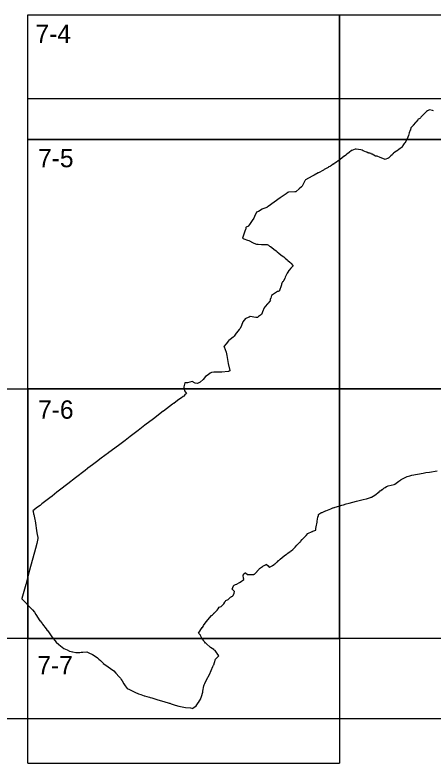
# Model space of a CAD drawing. Extents: x -449577 to -425530, y -1150048 to -1121091.
# Drawn here: x -443343.3 to -443133.6, y -1126653.4 to -1126278.4 of the extents above; entities that cross this region are included whole.
import ezdxf

# ---------------------------------------------------------------- set-up
doc = ezdxf.new("R2010")
doc.units = 0
for name, color, linetype in [('Vrstva 1', 7, 'Continuous'), ('Vrstva 10', 7, 'Continuous'), ('Vrstva 4', 7, 'Continuous')]:
    doc.layers.add(name, color=color, linetype=linetype)

msp = doc.modelspace()

# ---------------------------------------------------------------- linework, layer by layer
at = {"layer": 'Vrstva 1'}
for points in [[(-443133.39, -1126326.41), (-443133.85, -1126326.32), (-443135.44, -1126326), (-443135.74, -1126326.11), (-443136.3, -1126326.46), (-443136.85, -1126326.78), (-443137.34, -1126327.24), (-443137.87, -1126327.73), (-443138.27, -1126328.12), (-443138.28, -1126328.13), (-443138.61, -1126328.47), (-443138.74, -1126328.61), (-443139.25, -1126329.16), (-443139.7, -1126329.71), (-443139.86, -1126329.9), (-443140.22, -1126330.33), (-443140.96, -1126330.66), (-443140.98, -1126330.66), (-443141.18, -1126330.91), (-443142.04, -1126331.93), (-443142.42, -1126332.38), (-443143.55, -1126333.74), (-443143.56, -1126333.75), (-443144.8, -1126334.92), (-443144.92, -1126335.76), (-443144.97, -1126336.13), (-443145.01, -1126336.23), (-443145.49, -1126337.58), (-443145.93, -1126338.82), (-443145.96, -1126338.9), (-443146.26, -1126339.59), (-443147.19, -1126341.77), (-443147.21, -1126341.78), (-443147.78, -1126342.46), (-443148.08, -1126342.81), (-443148.08, -1126342.82), (-443148.42, -1126343.36), (-443149.29, -1126344.75), (-443149.38, -1126344.89), (-443149.55, -1126345.02), (-443150.08, -1126345.41), (-443150.69, -1126345.86), (-443150.69, -1126345.86), (-443151.66, -1126346.49), (-443151.79, -1126346.58), (-443151.97, -1126346.7), (-443153.27, -1126347.56), (-443153.28, -1126347.57), (-443153.54, -1126347.83), (-443153.66, -1126347.95), (-443153.88, -1126348.18), (-443154.16, -1126348.46), (-443154.73, -1126349.03), (-443155.89, -1126350.19), (-443156.09, -1126350.27), (-443157.59, -1126350.84), (-443160.4, -1126349.72), (-443160.4, -1126349.73), (-443160.41, -1126349.75), (-443161.32, -1126349.37), (-443161.63, -1126349.24), (-443161.65, -1126349.24), (-443162.04, -1126349.24), (-443162.52, -1126349.24), (-443164.08, -1126348.25), (-443164.34, -1126348.12), (-443164.63, -1126347.96), (-443164.69, -1126347.93), (-443164.73, -1126347.91), (-443165.27, -1126347.68), (-443165.32, -1126347.68), (-443165.33, -1126347.68), (-443165.48, -1126347.67), (-443165.6, -1126347.66), (-443165.91, -1126347.64), (-443165.93, -1126347.64), (-443165.93, -1126347.64), (-443166.04, -1126347.6), (-443166.28, -1126347.5), (-443166.88, -1126347.25), (-443167.04, -1126347.18), (-443168.56, -1126346.45), (-443169.18, -1126346.27), (-443169.85, -1126346.07), (-443172.17, -1126345.64), (-443172.18, -1126345.64), (-443172.58, -1126345.75), (-443174.32, -1126346.33), (-443174.45, -1126346.44), (-443175.66, -1126347.4), (-443175.66, -1126347.4), (-443176.81, -1126348.27), (-443177.38, -1126348.7), (-443177.96, -1126349.14), (-443178.12, -1126349.26), (-443180.25, -1126350.9), (-443181.32, -1126351.72), (-443181.79, -1126352.06), (-443182.55, -1126352.57), (-443182.8, -1126352.73), (-443183.39, -1126353.12), (-443183.43, -1126353.15), (-443183.64, -1126353.29), (-443184.55, -1126353.89), (-443184.56, -1126353.89), (-443185.03, -1126354.15), (-443185.18, -1126354.23), (-443185.36, -1126354.33), (-443185.82, -1126354.58), (-443186, -1126354.69), (-443186.16, -1126354.78), (-443186.26, -1126354.84), (-443186.5, -1126354.98), (-443188.16, -1126355.92), (-443188.33, -1126356.01), (-443188.56, -1126356.14), (-443191.03, -1126357.54), (-443191.15, -1126357.61), (-443193.26, -1126358.74), (-443194.28, -1126359.29), (-443197.62, -1126361.1), (-443197.79, -1126361.4), (-443197.85, -1126361.51), (-443198.63, -1126362.97), (-443199.31, -1126364.29), (-443199.45, -1126364.42), (-443199.54, -1126364.5), (-443200.68, -1126365.54), (-443202.19, -1126366.92), (-443202.36, -1126367.07), (-443202.36, -1126367.08), (-443202.83, -1126367.09), (-443206.02, -1126367.18), (-443206.03, -1126367.18), (-443206.46, -1126367.47), (-443207.29, -1126368.04), (-443209.76, -1126369.7), (-443209.8, -1126369.72), (-443210.04, -1126369.9), (-443210.31, -1126370.1), (-443213.29, -1126372.23), (-443213.36, -1126372.28), (-443216.36, -1126374.46), (-443216.83, -1126374.8), (-443216.99, -1126374.86), (-443218.93, -1126375.58), (-443218.94, -1126375.58), (-443219.33, -1126375.82), (-443221.21, -1126376.98), (-443222.13, -1126377.19), (-443222.38, -1126377.7), (-443223.14, -1126379.21), (-443223.15, -1126379.22), (-443223.22, -1126379.48), (-443223.42, -1126380.32), (-443224.25, -1126381.43), (-443225.62, -1126383.38), (-443226.18, -1126384.19), (-443226.21, -1126384.21), (-443227.37, -1126384.85), (-443227.47, -1126384.91), (-443227.54, -1126385.3), (-443227.69, -1126386.11), (-443227.74, -1126386.3), (-443229.03, -1126389.88), (-443229.2, -1126390.36), (-443229.17, -1126390.35), (-443229.15, -1126390.34), (-443228.47, -1126390.6), (-443226.66, -1126391.26), (-443226.04, -1126391.55), (-443223.75, -1126392.63), (-443223.73, -1126392.63), (-443222.57, -1126393.1), (-443222.1, -1126393.28), (-443222.07, -1126393.29), (-443221.64, -1126393.32), (-443221.5, -1126393.33), (-443221.28, -1126393.35), (-443219.68, -1126393.45), (-443218.64, -1126393.52), (-443217.59, -1126393.49), (-443216.75, -1126393.46), (-443216.74, -1126393.46), (-443216.46, -1126393.61), (-443216.09, -1126393.87), (-443215.54, -1126394.25), (-443215.15, -1126394.53), (-443213.59, -1126395.67), (-443213.42, -1126395.79), (-443212.31, -1126396.71), (-443211.92, -1126397.03), (-443211.74, -1126397.18), (-443210.99, -1126397.79), (-443210.72, -1126398.02), (-443210.12, -1126398.51), (-443209.9, -1126398.69), (-443209.26, -1126399.11), (-443208.51, -1126399.61), (-443208.48, -1126399.63), (-443207.72, -1126400.31), (-443206.84, -1126401.09), (-443206.4, -1126401.47), (-443205.39, -1126402.36), (-443205.13, -1126402.59), (-443205.08, -1126402.64), (-443204.98, -1126402.74), (-443204.97, -1126402.75), (-443204.88, -1126402.85), (-443204.85, -1126402.88), (-443203.8, -1126404.11), (-443203.81, -1126404.12), (-443204.25, -1126404.61), (-443204.31, -1126404.68), (-443204.88, -1126405.31), (-443205.7, -1126406.37), (-443205.87, -1126406.58), (-443206.43, -1126407.3), (-443206.73, -1126407.83), (-443206.75, -1126407.87), (-443206.76, -1126407.89), (-443206.89, -1126408.17), (-443207.69, -1126409.84), (-443208, -1126410.48), (-443208.62, -1126411.77), (-443208.73, -1126412.01), (-443208.74, -1126412.01), (-443208.78, -1126412.04), (-443209.07, -1126412.24), (-443209.15, -1126412.28), (-443209.2, -1126412.38), (-443209.29, -1126412.58), (-443209.38, -1126412.86), (-443209.55, -1126413.42), (-443209.56, -1126413.44), (-443209.68, -1126413.94), (-443209.7, -1126414.01), (-443209.69, -1126414.07), (-443209.68, -1126414.15), (-443209.68, -1126414.22), (-443209.69, -1126414.27), (-443210.57, -1126416.6), (-443210.59, -1126416.65), (-443210.61, -1126416.69), (-443210.62, -1126416.7), (-443211.32, -1126417), (-443211.57, -1126417.11), (-443212.04, -1126417.35), (-443214.65, -1126419.04), (-443214.65, -1126419.04), (-443215.02, -1126420.35), (-443215.1, -1126420.61), (-443215.21, -1126421.03), (-443215.27, -1126421.24), (-443215.27, -1126421.25), (-443215.26, -1126421.25), (-443215.09, -1126421.41), (-443215.1, -1126421.42), (-443215.46, -1126421.81), (-443216.26, -1126422.81), (-443216.27, -1126422.82), (-443216.48, -1126423.07), (-443216.48, -1126423.08), (-443216.6, -1126423.23), (-443217.76, -1126424.58), (-443218.3, -1126425.21), (-443219.06, -1126427.16), (-443219.44, -1126428.18), (-443219.57, -1126428.53), (-443221.1, -1126429.63), (-443221.72, -1126430.07), (-443221.9, -1126430.11), (-443221.92, -1126430.11), (-443222.55, -1126430.02), (-443225.39, -1126429.6), (-443225.88, -1126429.84), (-443227.21, -1126430.48), (-443227.75, -1126430.74), (-443227.78, -1126430.77), (-443228.21, -1126431.18), (-443228.38, -1126431.4), (-443229.04, -1126432.25), (-443229.04, -1126432.26), (-443229.71, -1126434.06), (-443230.28, -1126435.56), (-443230.28, -1126435.56), (-443230.42, -1126435.78), (-443230.75, -1126436.15), (-443231.47, -1126436.95), (-443232.17, -1126437.72), (-443232.18, -1126437.74), (-443232.31, -1126437.93), (-443233.38, -1126439.5), (-443233.85, -1126439.88), (-443235.42, -1126441.14), (-443236.09, -1126441.68), (-443236.19, -1126441.76), (-443236.22, -1126441.8), (-443237.34, -1126443.23), (-443238.48, -1126444.54), (-443238.33, -1126444.71), (-443238.32, -1126444.74), (-443238.32, -1126444.75), (-443237.31, -1126447.51), (-443237.03, -1126449.17), (-443236.71, -1126451.12), (-443236.3, -1126453.08), (-443235.57, -1126456.58), (-443235.53, -1126456.78), (-443236.18, -1126457.12), (-443236.3, -1126457.19), (-443239.47, -1126457.45), (-443239.63, -1126457.45), (-443241.12, -1126457.42), (-443243.51, -1126457.4), (-443244.79, -1126457.67), (-443245.39, -1126457.94), (-443246.37, -1126458.74), (-443247.67, -1126459.61), (-443247.76, -1126459.72), (-443248.92, -1126461.14), (-443250.37, -1126462.48), (-443251.06, -1126462.8), (-443251.66, -1126463.08), (-443252.83, -1126463.01), (-443254.44, -1126462.16), (-443256.68, -1126462.83), (-443258.16, -1126462.8), (-443258.54, -1126464.91), (-443258.55, -1126464.93), (-443258.56, -1126465.02), (-443258.27, -1126466.83), (-443257.3, -1126468.15), (-443257.29, -1126468.17), (-443258.03, -1126468.92), (-443258.64, -1126469.48), (-443258.89, -1126469.71), (-443259.69, -1126470.34), (-443261.62, -1126471.57), (-443261.68, -1126471.61), (-443263.65, -1126473.14), (-443263.71, -1126473.18), (-443264.2, -1126473.56), (-443268.86, -1126477.02), (-443268.89, -1126477.05), (-443273.84, -1126480.81), (-443278.1, -1126484.06), (-443278.98, -1126484.72), (-443281.55, -1126486.66), (-443285.55, -1126489.79), (-443287.99, -1126491.66), (-443291.3, -1126494.19), (-443291.35, -1126494.23), (-443296.14, -1126497.74), (-443296.37, -1126497.92), (-443299.98, -1126500.6), (-443302.37, -1126502.42), (-443304.34, -1126503.9), (-443306.66, -1126505.65), (-443306.89, -1126505.82), (-443308.02, -1126506.71), (-443312.84, -1126510.51), (-443316.73, -1126513.46), (-443320.95, -1126516.71), (-443322.24, -1126517.71), (-443324.63, -1126519.59), (-443325.81, -1126520.51), (-443329.75, -1126523.56), (-443330.68, -1126524.27), (-443331.92, -1126525.23), (-443334.24, -1126527.03), (-443334.24, -1126527.03), (-443334.2, -1126527.21), (-443333.91, -1126528.59), (-443333.88, -1126528.75), (-443333.35, -1126531.29), (-443333.19, -1126532.02), (-443333.19, -1126532.06), (-443332.26, -1126537.94), (-443332.25, -1126537.97), (-443331.95, -1126539.7), (-443331.95, -1126539.72), (-443331.89, -1126540.09), (-443331.83, -1126540.51), (-443331.86, -1126540.88), (-443332.01, -1126541.61), (-443332.39, -1126543.4), (-443332.68, -1126544.58), (-443332.7, -1126544.63), (-443333.81, -1126548.8), (-443335.91, -1126556.68), (-443337.9, -1126563.9), (-443339.83, -1126571), (-443339.84, -1126571.04), (-443334.56, -1126576.64), (-443333.51, -1126577.77), (-443332.75, -1126578.99), (-443330.73, -1126582.05), (-443330.68, -1126582.12), (-443329.67, -1126583.53), (-443329.51, -1126583.74), (-443327.63, -1126586.22), (-443327.06, -1126586.96), (-443327.03, -1126587), (-443326.51, -1126587.72), (-443325.13, -1126589.62), (-443324.8, -1126590.07), (-443322.65, -1126592.79), (-443321.25, -1126594.01), (-443318.85, -1126595.99), (-443317.11, -1126596.74), (-443315.92, -1126597.26), (-443315.79, -1126597.31), (-443314.46, -1126597.59), (-443314.32, -1126597.62), (-443312.7, -1126597.95), (-443312.67, -1126597.95), (-443311.71, -1126597.93), (-443311.33, -1126597.93), (-443310.81, -1126597.92), (-443310.13, -1126597.91), (-443309.22, -1126597.87), (-443307.27, -1126597.71), (-443306.82, -1126597.78), (-443306.16, -1126598.13), (-443304.44, -1126599.08), (-443302.48, -1126600.18), (-443301.96, -1126600.66), (-443301.24, -1126601.34), (-443300.44, -1126602.09), (-443299.12, -1126603.39), (-443298.98, -1126603.49), (-443297.79, -1126604.34), (-443295.38, -1126606.05), (-443293.74, -1126607.23), (-443292.69, -1126608.41), (-443291.05, -1126610.23), (-443290.41, -1126610.94), (-443290.05, -1126611.53), (-443289.59, -1126612.27), (-443288.65, -1126613.74), (-443288.02, -1126614.66), (-443286.98, -1126616.1), (-443285.91, -1126616.61), (-443284.53, -1126617.26), (-443283.22, -1126617.87), (-443281.25, -1126618.76), (-443280.12, -1126619.11), (-443278.4, -1126619.68), (-443278.25, -1126619.73), (-443277.16, -1126620.05), (-443275.74, -1126620.47), (-443275.73, -1126620.47), (-443275.52, -1126620.53), (-443275.46, -1126620.55), (-443274.6, -1126620.81), (-443272.21, -1126621.5), (-443272.09, -1126621.54), (-443271.61, -1126621.68), (-443268.68, -1126622.55), (-443265.99, -1126623.38), (-443265.65, -1126623.48), (-443264.89, -1126623.71), (-443262.88, -1126624.33), (-443261.15, -1126624.88), (-443257.69, -1126625.62)], [(-443257.69, -1126625.62), (-443255.3, -1126625.81), (-443254.1, -1126626.04), (-443253.99, -1126625.95), (-443252.41, -1126624.68), (-443251.38, -1126623.2), (-443251.27, -1126623.05), (-443250.75, -1126622.29), (-443250.64, -1126622.12), (-443250.5, -1126621.89), (-443250.12, -1126621.26), (-443249.85, -1126620.43), (-443249.83, -1126620.36), (-443249.81, -1126620.31), (-443249.78, -1126620.2), (-443249.75, -1126620.11), (-443249.75, -1126620.1), (-443249.12, -1126617.9), (-443248.98, -1126617.38), (-443248.53, -1126614.63), (-443248.53, -1126614.63), (-443248.34, -1126614.19), (-443248.08, -1126613.57), (-443247.29, -1126611.74), (-443245.72, -1126609.09), (-443243.97, -1126604.96), (-443243.65, -1126604.32), (-443243.61, -1126604.19), (-443243.22, -1126603.09), (-443242.63, -1126601.42), (-443240.95, -1126599.71), (-443241.88, -1126598.47), (-443241.94, -1126598.38), (-443241.99, -1126598.32), (-443242.02, -1126598.28), (-443242.09, -1126598.18), (-443242.14, -1126598.1), (-443242.22, -1126597.98), (-443242.58, -1126597.46), (-443242.95, -1126597), (-443243.52, -1126596.63), (-443243.62, -1126596.57), (-443245.27, -1126595.5), (-443247.46, -1126593.56), (-443247.59, -1126593.39), (-443247.62, -1126593.35), (-443247.7, -1126593.25), (-443248.04, -1126592.83), (-443248.37, -1126592.42), (-443248.63, -1126592.1), (-443249.11, -1126591.51), (-443249.19, -1126591.41), (-443249.69, -1126590.45), (-443249.98, -1126589.89), (-443250.21, -1126589.46), (-443250.26, -1126589.37), (-443250.3, -1126589.32), (-443250.56, -1126589.03), (-443250.76, -1126588.8), (-443251.02, -1126588.51), (-443251.24, -1126588.26), (-443249.38, -1126585.52), (-443249.29, -1126585.4), (-443248.97, -1126584.95), (-443248.65, -1126584.51), (-443247.32, -1126582.68), (-443244.64, -1126579.42), (-443244.29, -1126579.1), (-443243.58, -1126578.4), (-443243.47, -1126578.31), (-443243.28, -1126578.17), (-443242.68, -1126577.69), (-443241.82, -1126576.85), (-443241.41, -1126576.09), (-443240.94, -1126575.22), (-443239.89, -1126574.98), (-443238.49, -1126573.55), (-443237.95, -1126572.7), (-443237.94, -1126572.69), (-443237.94, -1126572.67), (-443237.73, -1126572.34), (-443237.68, -1126572.26), (-443237.44, -1126571.87), (-443236.28, -1126571.43), (-443235.26, -1126570.25), (-443234.73, -1126570.05), (-443234.61, -1126570), (-443234.19, -1126569.84), (-443233.97, -1126569.45), (-443233.92, -1126569.36), (-443233.75, -1126569.06), (-443233.34, -1126568.32), (-443233.14, -1126567.41), (-443233.14, -1126567.39), (-443233.13, -1126567.38), (-443234.18, -1126566.39), (-443234.2, -1126566.38), (-443234.21, -1126566.36), (-443234.26, -1126566.32), (-443233.61, -1126564.52), (-443233.54, -1126564.32), (-443233.38, -1126564.26), (-443232.65, -1126563.97), (-443231.96, -1126563.7), (-443231.84, -1126563.65), (-443230.63, -1126562.94), (-443230.51, -1126562.86), (-443230.51, -1126562.86), (-443230.5, -1126562.85), (-443230.38, -1126562.78), (-443228.52, -1126561.38), (-443228.52, -1126561.34), (-443228.55, -1126561.18), (-443228.62, -1126560.7), (-443228.68, -1126560.35), (-443228.78, -1126559.73), (-443228.8, -1126559.62), (-443228.82, -1126559.49), (-443228.84, -1126559.32), (-443228.87, -1126559.18), (-443228.33, -1126558.62), (-443227.77, -1126558.05), (-443227.73, -1126558), (-443227.59, -1126558.1), (-443226.59, -1126558.89), (-443225.91, -1126558.9), (-443225.85, -1126558.9), (-443225.6, -1126558.91), (-443225.44, -1126558.91), (-443224.13, -1126558.93), (-443223.5, -1126558.95), (-443223.23, -1126558.79), (-443223.2, -1126558.77), (-443223.08, -1126558.7), (-443222.94, -1126558.61), (-443222.9, -1126558.58), (-443222.36, -1126557.98), (-443222.25, -1126557.86), (-443222.16, -1126557.76), (-443221.99, -1126557.58), (-443221.91, -1126557.49), (-443221.8, -1126557.37), (-443221.77, -1126557.33), (-443221.74, -1126557.3), (-443221.69, -1126557.24), (-443221.6, -1126557.13), (-443221.2, -1126556.63), (-443220.99, -1126556.37), (-443220.74, -1126556.05), (-443220.63, -1126555.97), (-443219.17, -1126554.9), (-443218.96, -1126554.77), (-443217.6, -1126554), (-443217.2, -1126553.77), (-443217.2, -1126553.77), (-443217.06, -1126553.92), (-443216.35, -1126554.63), (-443215.98, -1126555.01), (-443215.8, -1126555.18), (-443215.65, -1126555.33), (-443215.56, -1126555.29), (-443214.28, -1126554.52), (-443214.19, -1126554.47), (-443213.26, -1126553.91), (-443213.22, -1126553.88), (-443212.89, -1126553.59), (-443212.84, -1126553.55), (-443212.67, -1126553.4), (-443212.66, -1126553.39), (-443212.66, -1126553.39), (-443212.62, -1126553.35), (-443212.58, -1126553.31), (-443211.69, -1126552.5), (-443211.67, -1126552.49), (-443211.08, -1126551.95), (-443210.97, -1126551.86), (-443210.86, -1126551.76), (-443210.86, -1126551.76), (-443210.85, -1126551.76), (-443210.85, -1126551.76), (-443210.85, -1126551.75), (-443210.84, -1126551.75), (-443210.83, -1126551.74), (-443210.83, -1126551.74), (-443210.82, -1126551.73), (-443210.82, -1126551.73), (-443210.81, -1126551.73), (-443210.81, -1126551.73), (-443210.23, -1126551.24), (-443208.24, -1126549.56), (-443207.04, -1126548.71), (-443206.92, -1126548.63), (-443206.87, -1126548.59), (-443206.85, -1126548.58), (-443206.8, -1126548.55), (-443206.44, -1126548.28), (-443205.2, -1126547.34), (-443205.02, -1126547.2), (-443204.81, -1126547.04), (-443204.79, -1126547.02), (-443203.91, -1126546.35), (-443203.56, -1126546.08), (-443203.51, -1126546.02), (-443203.42, -1126545.92), (-443202.78, -1126545.24), (-443201.88, -1126544.26), (-443200.52, -1126542.85), (-443200.3, -1126542.62), (-443200.05, -1126542.34), (-443199.21, -1126541.39), (-443198.92, -1126541.07), (-443198.72, -1126540.86), (-443198.43, -1126540.54), (-443197.25, -1126539.35), (-443196.32, -1126538.33), (-443194.26, -1126537.32), (-443194.1, -1126537.27), (-443193.9, -1126537.19), (-443192.46, -1126536.7), (-443192.31, -1126535.83), (-443192.15, -1126534.96), (-443191.73, -1126532.59), (-443191.65, -1126532.12), (-443191.32, -1126530.24), (-443191.12, -1126529.36), (-443191.09, -1126529.24), (-443191.04, -1126529.05), (-443191.03, -1126529.01), (-443191.01, -1126528.94), (-443191, -1126528.9), (-443190.99, -1126528.85), (-443190.98, -1126528.81), (-443190.97, -1126528.79), (-443190.91, -1126528.58), (-443189.83, -1126528.04), (-443189.54, -1126527.9), (-443189.52, -1126527.89), (-443189.27, -1126527.76), (-443189.22, -1126527.74), (-443187.45, -1126527.02), (-443187.42, -1126527.01), (-443187.39, -1126526.99), (-443186.59, -1126526.68), (-443185.63, -1126526.28), (-443184.82, -1126525.94), (-443183.88, -1126525.55), (-443183.8, -1126525.52), (-443183.19, -1126525.28), (-443183.34, -1126525.44), (-443183.1, -1126525.35), (-443182.61, -1126525.15), (-443182.08, -1126524.99), (-443180.38, -1126524.47), (-443179.79, -1126524.3), (-443179.34, -1126524.18), (-443178.45, -1126523.93), (-443177.14, -1126523.55), (-443175.6, -1126523.09), (-443172.06, -1126522.22), (-443169.29, -1126521.55), (-443168.62, -1126521.34), (-443167.13, -1126520.98), (-443166.92, -1126520.92), (-443165.49, -1126520.53), (-443164.89, -1126520.27), (-443164.67, -1126520.17), (-443164.51, -1126520.11), (-443163.69, -1126519.66), (-443163.63, -1126519.62), (-443162.32, -1126518.84), (-443161.17, -1126517.79), (-443160.52, -1126517.29), (-443160.39, -1126517.18), (-443160.37, -1126517.17), (-443160.21, -1126517.04), (-443160.06, -1126516.94), (-443159.26, -1126516.38), (-443159.2, -1126516.34), (-443159.13, -1126516.29), (-443158.62, -1126515.94), (-443158.25, -1126515.68), (-443157.59, -1126515.22), (-443157, -1126514.81), (-443156.84, -1126514.84), (-443156.83, -1126514.84), (-443156.81, -1126514.82), (-443156.08, -1126514.43), (-443153.12, -1126513.85), (-443152.7, -1126513.7), (-443150.67, -1126512.07), (-443150.2, -1126511.73), (-443150.17, -1126511.71), (-443149.81, -1126511.45), (-443149.63, -1126511.33), (-443148.24, -1126510.63), (-443146.83, -1126509.99), (-443146.53, -1126509.84), (-443145.27, -1126509.38), (-443144.27, -1126509.13), (-443138.56, -1126508.07), (-443137.14, -1126507.81), (-443135.43, -1126507.56), (-443131.56, -1126506.99)]]:
    msp.add_lwpolyline(points, dxfattribs=at)
at = {"layer": 'Vrstva 10'}
msp.add_lwpolyline([(-443024.3, -1126320.23), (-443024.3, -1126631.21), (-443357.17, -1126631.21), (-443357.17, -1126465.91), (-443336.8, -1126465.91), (-443336.8, -1126340.91), (-443336.8, -1126320.23), (-443024.3, -1126320.23)], dxfattribs=at)
at = {"layer": 'Vrstva 4'}
for p, q in [((-443336.8, -1126278.41), (-443024.3, -1126278.41)), ((-443336.8, -1126653.41), (-443180.55, -1126653.41))]:
    msp.add_line(p, q, dxfattribs=at)
for points in [[(-443180.55, -1126278.41), (-443180.55, -1126340.91), (-443336.8, -1126340.91), (-443336.8, -1126278.41)], [(-443024.3, -1126278.41), (-443024.3, -1126340.91), (-443180.55, -1126340.91), (-443180.55, -1126278.41)], [(-443414.93, -1126465.91), (-443336.8, -1126465.91), (-443336.8, -1126590.91), (-443414.93, -1126590.91)], [(-443336.8, -1126653.41), (-443336.8, -1126590.91), (-443180.55, -1126590.91), (-443180.55, -1126653.41)]]:
    msp.add_lwpolyline(points, dxfattribs=at)
for points in [[(-443180.55, -1126340.91), (-443180.55, -1126465.91), (-443336.8, -1126465.91), (-443336.8, -1126340.91)], [(-443024.3, -1126340.91), (-443024.3, -1126465.91), (-443180.55, -1126465.91), (-443180.55, -1126340.91)], [(-443180.55, -1126465.91), (-443180.55, -1126590.91), (-443336.8, -1126590.91), (-443336.8, -1126465.91)], [(-443024.3, -1126465.91), (-443024.3, -1126590.91), (-443180.55, -1126590.91), (-443180.55, -1126465.91)]]:
    msp.add_lwpolyline(points, close=True, dxfattribs=at)

# ---------------------------------------------------------------- texts
at = {"layer": 'Vrstva 1'}
for s, p in [('7-4', (-443332.99, -1126292.41)), ('7-5', (-443331.68, -1126354.75)), ('7-6', (-443331.68, -1126480.82)), ('7-7', (-443332.04, -1126608.99))]:
    msp.add_text(s, height=9.2, dxfattribs=at).set_placement(p)

doc.saveas('drawing.dxf')
